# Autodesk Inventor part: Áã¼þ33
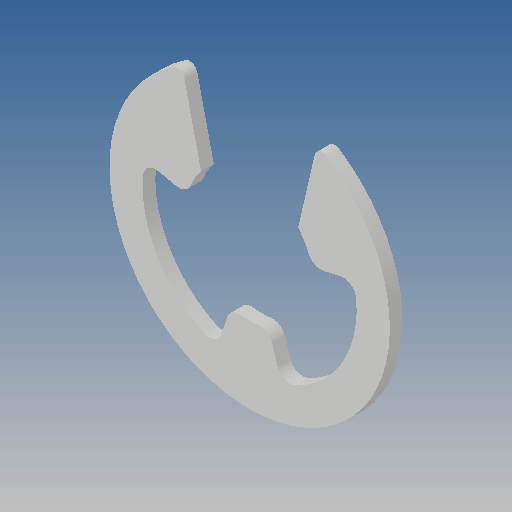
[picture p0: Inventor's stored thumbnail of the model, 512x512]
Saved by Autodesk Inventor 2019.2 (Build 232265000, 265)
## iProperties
Created: 2013-07
Part Number: Áã¼þ33
Material: Ogólny
Document SubType Name: Modeling
Designer: CADENGINEERING4
Density: 1 g/cm^3
Appearance: Domyślna
Author: CADENGINEERING4
Revision Number: ÈÎºÎ
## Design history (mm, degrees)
feature "Í¹Ì¨-À­Éì1"
node "Bryła1"
